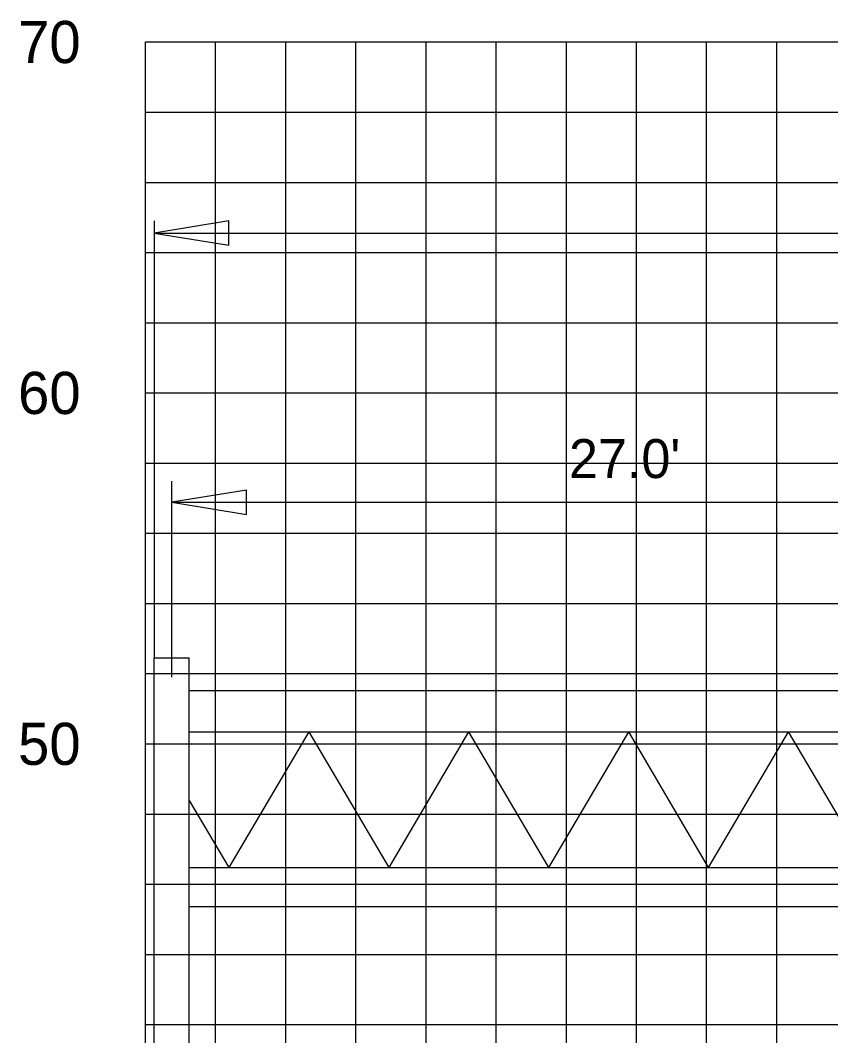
# Model space of a CAD drawing. Extents: x 1797809 to 2198143, y 249608 to 1237864.
# Drawn here: x 2195654.22 to 2195677.32, y 1237194.79 to 1237223.72 of the extents above; entities that cross this region are included whole.
import ezdxf

# ---------------------------------------------------------------- set-up
doc = ezdxf.new("R2010")
doc.units = 0
for name, color, linetype in [('3', 7, 'Continuous'), ('31', 7, 'Continuous'), ('60', 7, 'Continuous'), ('Default', 7, 'Continuous'), ('GSDIMS', 7, 'Continuous'), ('GSSHT', 7, 'Continuous'), ('Level 55', 7, 'Continuous')]:
    doc.layers.add(name, color=color, linetype=linetype)

msp = doc.modelspace()

# ---------------------------------------------------------------- linework, layer by layer
at = {"layer": '3'}
for p, q in [((2195658.037, 1237218.01), (2195658.037, 1237205.554)), ((2195658.037, 1237217.662), (2195750.274, 1237217.662)), ((2195658.037, 1237181.164), (2195658.037, 1237205.554)), ((2195659.037, 1237181.164), (2195659.037, 1237205.554))]:
    msp.add_line(p, q, dxfattribs=at)
at = {"layer": '60'}
msp.add_line((2195657.787, 1237163.106), (2195657.787, 1237223.106), dxfattribs=at)
at = {"layer": 'Default'}
msp.add_line((2195658.537, 1237205.002), (2195658.537, 1237210.587), dxfattribs=at)
at = {"layer": 'GSDIMS'}
for p, q in [((2195658.537, 1237209.99), (2195685.537, 1237209.99)), ((2195658.037, 1237205.554), (2195659.037, 1237205.554)), ((2195659.037, 1237204.628), (2195685.537, 1237204.628)), ((2195659.037, 1237203.444), (2195685.537, 1237203.444)), ((2195662.442, 1237203.444), (2195660.164, 1237199.581)), ((2195662.442, 1237203.444), (2195664.721, 1237199.581)), ((2195666.999, 1237203.444), (2195664.721, 1237199.581)), ((2195666.999, 1237203.444), (2195669.278, 1237199.581)), ((2195671.556, 1237203.444), (2195669.278, 1237199.581)), ((2195671.556, 1237203.444), (2195673.835, 1237199.581)), ((2195676.113, 1237203.444), (2195673.835, 1237199.581)), ((2195676.113, 1237203.444), (2195678.392, 1237199.581)), ((2195659.037, 1237201.49), (2195660.164, 1237199.581)), ((2195659.037, 1237199.581), (2195685.633, 1237199.581)), ((2195659.037, 1237198.471), (2195710.292, 1237198.471))]:
    msp.add_line(p, q, dxfattribs=at)
for points in [[(2195658.037, 1237217.662), (2195660.166, 1237217.315), (2195660.166, 1237218.01)], [(2195658.537, 1237209.99), (2195660.666, 1237209.643), (2195660.666, 1237210.338)]]:
    msp.add_lwpolyline(points, close=True, dxfattribs=at)
at = {"layer": 'GSSHT'}
for p, q in [((2195657.787, 1237223.106), (2195787.787, 1237223.106)), ((2195659.787, 1237163.106), (2195659.787, 1237223.106)), ((2195661.787, 1237163.106), (2195661.787, 1237223.106)), ((2195663.787, 1237163.106), (2195663.787, 1237223.106)), ((2195665.787, 1237163.106), (2195665.787, 1237223.106)), ((2195667.787, 1237163.106), (2195667.787, 1237223.106)), ((2195669.787, 1237163.106), (2195669.787, 1237223.106)), ((2195671.787, 1237163.106), (2195671.787, 1237223.106)), ((2195673.787, 1237163.106), (2195673.787, 1237223.106)), ((2195675.787, 1237163.106), (2195675.787, 1237223.106)), ((2195657.787, 1237221.106), (2195787.787, 1237221.106)), ((2195657.787, 1237219.106), (2195787.787, 1237219.106)), ((2195657.787, 1237217.106), (2195787.787, 1237217.106)), ((2195657.787, 1237215.106), (2195787.787, 1237215.106)), ((2195657.787, 1237213.106), (2195787.787, 1237213.106)), ((2195657.787, 1237211.106), (2195787.787, 1237211.106)), ((2195657.787, 1237209.106), (2195787.787, 1237209.106)), ((2195657.787, 1237207.106), (2195787.787, 1237207.106)), ((2195657.787, 1237205.106), (2195787.787, 1237205.106)), ((2195657.787, 1237203.106), (2195787.787, 1237203.106)), ((2195657.787, 1237201.106), (2195787.787, 1237201.106)), ((2195657.787, 1237199.106), (2195787.787, 1237199.106)), ((2195657.787, 1237197.106), (2195787.787, 1237197.106)), ((2195657.787, 1237195.106), (2195787.787, 1237195.106))]:
    msp.add_line(p, q, dxfattribs=at)

# ---------------------------------------------------------------- texts
at = {"layer": '31'}
for s, p in [('70', (2195654.154, 1237222.506)), ('60', (2195654.154, 1237212.506)), ('50', (2195654.154, 1237202.506))]:
    msp.add_text(s, height=1.2, dxfattribs=at).set_placement(p)
at = {"layer": 'Level 55'}
msp.add_text("27.0'", height=1.1105, dxfattribs=at).set_placement((2195669.862, 1237210.679))

doc.saveas('drawing.dxf')
